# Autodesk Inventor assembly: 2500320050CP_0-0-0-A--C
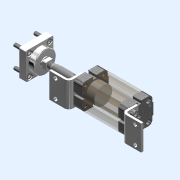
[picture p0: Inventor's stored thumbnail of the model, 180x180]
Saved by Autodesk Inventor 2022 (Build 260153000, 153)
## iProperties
Category: PARTsolutions
Company: METALWORK
Part Number: 2500320050CP_0-0-0-A--C
Catalog Web Link: www.cadenas.de
Description: Compact cylinder series CMPC ISO male piston rod-
Vendor: METALWORK
Document SubType Name: Assembly
Designer: partserver
Manufacturer: METALWORK
Mass: 164.753 g
Surface Area: 678.716 cm^2
Volume: 164.753 cm^3
PSOL_IDENT_0: {$CADENAS_DATA\23d-libs\metalwork\actuators\comp_cyl_ser_cmpc\cmpc_iso_male\cmpc_iso_male_asmtab.prj
PSOL_IDENT_1: },284 {VTYP=3D},{STYP=ASSTAB},{NB=2500320050CP/0-0-0-A--},{LINA=2500320050CP},{NN=Compact cylinder s
PSOL_IDENT_2: eries CMPC ISO male piston rod},{DATE=18.06.2021 08:06:07},{GEOMDATE=21.01.2021 14:41:13},{VERSION=}
PSOL_IDENT_3: ,{LINEID=50},{WBVAR=VE,EX,NS,HUB,HUBST,MAT,SE,AC1,AC2,AC3,AC4,AC5},{WBNUMERIC=HUB,HUBST}  {NB=250032
PSOL_IDENT_4: 0050CP/0-0-0-A--},{LINA=2500320050CP},{KT=DUMMY},{IDNR=},{CODE=2500320050CP},{DI=32},{DX=32},{TP=Cen
PSOL_IDENT_5: tre distance to ISO, male rod},{TYPE=25},{VE=0},{VX='0','Double-acting','1','Double-acting, through-
PSOL_IDENT_6: rod','2','Double-acting, perfored through-rod','3','Single-acting, retracted rod','4','Single-acting
PSOL_IDENT_7: , extended rod','5','Single-acting, through-rod','6','Single-acting, perfored through-rod','A','Doub
PSOL_IDENT_8: le-acting, through-rod, non-rotating'},{EX=0},{EXX= '0','Standard', 'S','Non-magnetic', 'G','No stic
PSOL_IDENT_9: k-slip' },{NS=0},{NX='0','Standard','A','Tandem 2 stages','B','Tandem 3 stages','C','Tandem 4 stages'
PSOL_IDENT_10: ,'P','1st stage','R','2nd stage','T','3rd stage'},{HUB=50},{HUBX1=[5:300]},{HUBX2=050},{HUBST=0},{MA
PSOL_IDENT_11: T=C},{MX= 'C','C45 chromed rod', 'X','Stainless steel rod', 'A','C45 chromed rod, aluminium piston',
PSOL_IDENT_12: 'Z','Stainless steel piston rod and nut, aluminium piston' },{SE=P},{VA=31},{VB=10},{VBA=10},{VC=20
PSOL_IDENT_13: },{VOCF=2},{AC1=0},{AC1X=<'0','','blank.jpg'>, 'S','PISTON ROD NUT - MODEL S','s.jpg', 'GA-M','ROD E
PSOL_IDENT_14: YE - MODEL GA-M','ga_m.jpg','GA','COMPENSATION JOINT - MODEL GA','ga.jpg','GK-M','FORK - MODEL GK-M'
PSOL_IDENT_15: ,'gk_m.jpg','GA-K','SELF ALIGNING ROD COUPLER - MODEL GA-K','ga_k.jpg' },{AC2=0},{AC2X=<'0','','blan
PSOL_IDENT_16: k.jpg'>,'B','HINGE - MODEL B','b.jpg','B+GL','HINGE - MODEL B + GL','b_gl.jpg','BA','HINGE - MODEL B
PSOL_IDENT_17: A','ba.jpg' },{AC3=A},{AC3X='0','','blank.jpg','A','FOOT - MODEL A','a.jpg','X','FLANGE FOR OPPOSITE
PSOL_IDENT_18: CYLINDERS','x.jpg','CF','FRONT FLANGE - MODEL C','cf.jpg','CR','REAR FLANGE - MODEL C','cr.jpg' },{
PSOL_IDENT_19: AC3Y=A},{AC4=},{AC5=},{AC45X='','','blank.jpg','W0952025390','HALL N.O. sensor, vertical insertion 2
PSOL_IDENT_20: .5 m','sov.jpg','W0952225390','HALL N.O. sensor, vertical insertion 2.5 m robotics','sov.jpg','W0952
PSOL_IDENT_21: 029394','HALL N.O. sensor, vertical insertion 300 mm M8 robotics','sov.jpg','W0952022180','REED N.O.
PSOL_IDENT_22: sensor, vertical insertion 2.5 m','sov.jpg','W0952222180','REED N.O. sensor, vertical insertion 2.5
PSOL_IDENT_23: m robotics','sov.jpg','W0952028184','REED N.O. sensor, vertical insertion 300 mm M8 robotics','sov.
PSOL_IDENT_24: jpg','W0952125556','HALL N.O. sensor, vertical insertion 2 m ATEX','sov.jpg','W0952025500','HALL N.O
PSOL_IDENT_25: . sensor, vertical insertion HS 2.5 m','sov.jpg','W0952029504','HALL N.O. sensor, vertical insertion
PSOL_IDENT_26: HS 300 mm M8','sov.jpg','W0952022500','REED N.O. sensor, vertical insertion HS 2.5 m','sov.jpg','W0
PSOL_IDENT_27: 952128184','REED N.O. sensor, vertical insertion HS 300 mm M8','sov.jpg','W095414','REED sensor, T7
PSOL_IDENT_28: SQUARED 2 wires 2.5 m','ssq.jpg','W095415','REED sensor, T7 SQUARED 2 wires 5 m','ssq.jpg','W095416'
PSOL_IDENT_29: ,'REED sensor, T7 SQUARED 2 wires 10 m','ssq.jpg','W09541C','REED sensor, T7 SQUARED 2 wires 2.5 m r
PSOL_IDENT_30: obotics','ssq.jpg','W095411','REED sensor, T7 SQUARED 2 wires 300 mm M8 robotics','ssq.jpg','W095434'
PSOL_IDENT_31: ,'HALL sensor, T7 SQUARED 3 wires 2.5 m','ssq.jpg','W095435','HALL sensor, T7 SQUARED 3 wires 5 m','
PSOL_IDENT_32: ssq.jpg','W09543C','HALL sensor, T7 SQUARED 3 wires 2.5 m robotics','ssq.jpg','W095431','HALL sensor
PSOL_IDENT_33: , T7 SQUARED 3 wires 300 mm M8 robotics','ssq.jpg','W0955A9','HALL sensor, T8 SQUARED 3 wires ATEX 2
PSOL_IDENT_34: m SH.OV.','ssq.jpg'},{INFO=Catalogue},{PPATH=cmpc_iso_male_asmtpl.prj},{A=47},{B=32.5},{B1=},{B2=},
PSOL_IDENT_35: {B3=},{C=12},{C1=},{CH=10},{CH1=17},{D=48.5},{E=6},{F=4},{G=44.5},{H=7.5},{H1=37},{L=4},{N=50.5},{N1=
PSOL_IDENT_36: },{N2=},{O=M6},{O1=5.2},{P1=},{P2=},{Q=G1/8},{R=M10x1.25},{S=22},{S1=6.0},{T=},{U=},{V=},{Z=},{WG=40
PSOL_IDENT_37: 4.50},{WGX=246},{VER=12},{ACALG1=},{ACALG2=},{ACALG3= _ A},{DIALG=32},{SEX= 'P', 'Polyurethane' }
NB: 2500320050CP/0-0-0-A--
NN: Compact cylinder series CMPC ISO male piston rod
NBSYN: $CODE./$HUBST.-$AC1.-$AC2.-$AC3.-$AC4.-$AC5.
LINA: 2500320050CP
CATALOG: Metalwork
CODE: 2500320050CP
DI: 32
TP: Centre distance to ISO, male rod
VE: Double-acting
EX: Standard
HUB: 50
HUBST: 0
MAT: C45 chromed rod
SE: Polyurethane
AC3: FOOT - MODEL A
INFO: Catalogue
A: 47
B: 32.5
C: 12
CH: 10
CH1: 17
D: 48.5
E: 6
F: 4
G: 44.5
H: 7.5
H1: 37
L: 4
N: 50.5
O: M6
O1: 5.2
Q: G1/8
R: M10x1.25
S: 22
S1: 6
WG: 404.5
SUPPLIER: METALWORK
ARTICLENO: 2500320050CP/0-0-0-A--
BOMINFO: 2500320050CP
CREATOR: CADENAS GmbH
Title: 2500320050CP
Author: Cadenas PARTsolutions
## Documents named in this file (9)
- C:\Users\admin\Desktop\inventor\sistema_piegatura2\2500320050CP_0-0-0-A--C.iam
- C:\Users\admin\Desktop\inventor\sistema_piegatura2\250-32-CMPC-HF.ipt
- C:\Users\admin\Desktop\inventor\sistema_piegatura2\250-32_50-CMPC-BR.ipt
- C:\Users\admin\Desktop\inventor\sistema_piegatura2\250-32-CMPC-HR.ipt
- C:\Users\admin\Desktop\inventor\sistema_piegatura2\W0950322001-31_.ipt
- C:\Users\admin\Desktop\inventor\sistema_piegatura2\Cylinder head screw DIN 912 M6x16.ipt
- C:\Users\admin\Desktop\inventor\sistema_piegatura2\250-32_50-CMPC-PR.ipt
- C:\Users\admin\Desktop\inventor\sistema_piegatura2\W0950326021-13.ipt
- C:\Users\admin\Desktop\inventor\sistema_piegatura2\Cylinder head screw DIN 912 M6x20.ipt
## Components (15 placed, 8 different names)
1. 250-32-CMPC-HF:1 — Coincidente:8, Coincidente:9, Coincidente:10, Coincidente:11, Coincidente:13, Coincidente:14, Coincidente:15, Coincidente:16, Coincidente:17, Angolo:1, Angolo:2
2. 250-32_50-CMPC-BR:1 — Coincidente:1, Coincidente:2, Coincidente:3, Coincidente:8, Coincidente:9, Coincidente:10
3. 250-32-CMPC-HR:1 — Coincidente:1, Coincidente:2, Coincidente:3, Coincidente:5, Coincidente:6, Coincidente:7, Coincidente:12, drive_Coincidente:19
4. W0950322001-31_:1 — Coincidente:4, Coincidente:5, Coincidente:6, Coincidente:7, Rotazionale:1, Rotazionale:2
5. Cylinder head screw DIN 912 M6x16:1 — Coincidente:4, Rotazionale:2
6. Cylinder head screw DIN 912 M6x16:2 — Rotazionale:1
7. W0950322001-31_:2 — Coincidente:13, Coincidente:14, Coincidente:15, Coincidente:16, Coincidente:17, Rotazionale:3, Rigido:1
8. Cylinder head screw DIN 912 M6x16:3 — Rotazionale:3
9. Cylinder head screw DIN 912 M6x16:4 — Rigido:1
10. W0950326021-13:1 — Coincidente:18, Angolo:2, Rotazionale:4, Rotazionale:5, Rigido:2, Rotazionale:6, Rotazionale:7
11. 250-32_50-CMPC-PR:1 — Coincidente:11, Coincidente:12, Angolo:1, Coincidente:18, Rotazionale:4, drive_Coincidente:19
12. Cylinder head screw DIN 912 M6x20:1
13. Cylinder head screw DIN 912 M6x20:2
14. Cylinder head screw DIN 912 M6x20:3
15. Cylinder head screw DIN 912 M6x20:4
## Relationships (30: Mate 19, RevoluteJoint 7, WeldJoint 2, Angle 2)
- Coincidente:1 [Mate]: 250-32_50-CMPC-BR:1 ↔ 250-32-CMPC-HR:1
- Coincidente:2 [Mate]: 250-32_50-CMPC-BR:1 ↔ 250-32-CMPC-HR:1
- Coincidente:3 [Mate]: 250-32_50-CMPC-BR:1 ↔ 250-32-CMPC-HR:1
- Coincidente:4 [Mate]: W0950322001-31_:1 ↔ Cylinder head screw DIN 912 M6x16:1
- Coincidente:5 [Mate]: 250-32-CMPC-HR:1 ↔ W0950322001-31_:1
- Coincidente:6 [Mate]: 250-32-CMPC-HR:1 ↔ W0950322001-31_:1
- Coincidente:7 [Mate]: 250-32-CMPC-HR:1 ↔ W0950322001-31_:1
- Rotazionale:1 [RevoluteJoint]: W0950322001-31_:1 ↔ Cylinder head screw DIN 912 M6x16:2
- Rotazionale:2 [RevoluteJoint]: W0950322001-31_:1 ↔ Cylinder head screw DIN 912 M6x16:1
- Coincidente:8 [Mate]: 250-32-CMPC-HF:1 ↔ 250-32_50-CMPC-BR:1
- Coincidente:9 [Mate]: 250-32-CMPC-HF:1 ↔ 250-32_50-CMPC-BR:1
- Coincidente:10 [Mate]: 250-32-CMPC-HF:1 ↔ 250-32_50-CMPC-BR:1
- Coincidente:11 [Mate]: 250-32-CMPC-HF:1 ↔ 250-32_50-CMPC-PR:1
- Coincidente:12 [Mate]: 250-32-CMPC-HR:1 ↔ 250-32_50-CMPC-PR:1
- Coincidente:13 [Mate]: 250-32-CMPC-HF:1 ↔ W0950322001-31_:2
- Coincidente:14 [Mate]: 250-32-CMPC-HF:1 ↔ W0950322001-31_:2
- Coincidente:15 [Mate]: 250-32-CMPC-HF:1 ↔ W0950322001-31_:2
- Coincidente:16 [Mate]: 250-32-CMPC-HF:1 ↔ W0950322001-31_:2
- Coincidente:17 [Mate]: 250-32-CMPC-HF:1 ↔ W0950322001-31_:2
- Rotazionale:3 [RevoluteJoint]: W0950322001-31_:2 ↔ Cylinder head screw DIN 912 M6x16:3
- Rigido:1 [WeldJoint]: W0950322001-31_:2 ↔ Cylinder head screw DIN 912 M6x16:4
- Angolo:1 [Angle]: 250-32-CMPC-HF:1 ↔ 250-32_50-CMPC-PR:1
- Coincidente:18 [Mate]: W0950326021-13:1 ↔ 250-32_50-CMPC-PR:1
- Angolo:2 [Angle]: 250-32-CMPC-HF:1 ↔ W0950326021-13:1
- Rotazionale:4 [RevoluteJoint]: W0950326021-13:1 ↔ 250-32_50-CMPC-PR:1
- drive_Coincidente:19 [Mate]: 250-32-CMPC-HR:1 ↔ 250-32_50-CMPC-PR:1
- Rotazionale:5 [RevoluteJoint]: W0950326021-13:1
- Rigido:2 [WeldJoint]: W0950326021-13:1
- Rotazionale:6 [RevoluteJoint]: W0950326021-13:1
- Rotazionale:7 [RevoluteJoint]: W0950326021-13:1
